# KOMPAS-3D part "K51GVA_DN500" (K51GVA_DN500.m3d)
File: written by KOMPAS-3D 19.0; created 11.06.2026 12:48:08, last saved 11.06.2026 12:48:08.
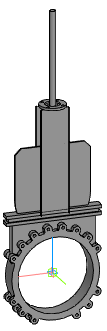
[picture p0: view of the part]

Document properties: Автор: Энергия; Полное имя файла: Z:\3.Личные\kachalov\001_3d для проектировщиков\2.6 Тип_K51GVA. Задвижка\_stp\_stp_K51GVA_DN50-DN1000_с фланцем\K51GVA_DN500.m3d

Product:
- Part/product: K51GVA_DN500

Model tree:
1. Операция без истории:1  (labels: K51GVA_DN500)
